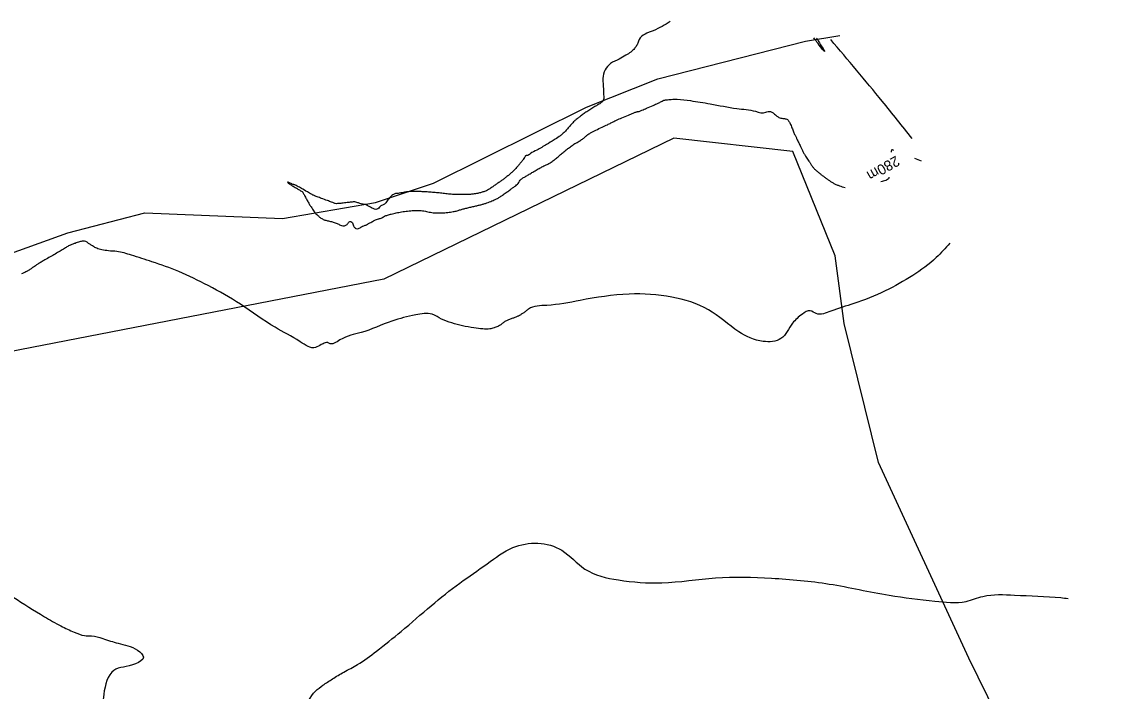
# Model space of a CAD drawing. Extents: x -478495 to -472450, y -1118050 to -1113745.
# Drawn here: x -473729.7 to -473541.9, y -1114845.9 to -1114729.7 of the extents above; entities that cross this region are included whole.
import ezdxf

# ---------------------------------------------------------------- set-up
doc = ezdxf.new("R2010")
doc.units = 0
for name, color, linetype in [('hranice kú', 7, 'Continuous'), ('ObPÚ', 7, 'Continuous'), ('vodní plochy', 7, 'Continuous'), ('Vrstevnice_hlavni', 7, 'Continuous'), ('Vrstevnice_popis', 7, 'Continuous'), ('Vrstevnice_vedlejsi', 7, 'Continuous')]:
    doc.layers.add(name, color=color, linetype=linetype)

msp = doc.modelspace()

# ---------------------------------------------------------------- linework, layer by layer
at = {"layer": 'hranice kú'}
for p, q in [((-473616.54, -1114749.9), (-473666.88, -1114774.39)), ((-473595.9, -1114752.21), (-473616.54, -1114749.9)), ((-473588.58, -1114770.34), (-473595.9, -1114752.21)), ((-473587.03, -1114782.1), (-473588.58, -1114770.34)), ((-473666.88, -1114774.39), (-473748.84, -1114790.3)), ((-473581.05, -1114806.21), (-473587.03, -1114782.1)), ((-473565.42, -1114840.17), (-473581.05, -1114806.21)), ((-473541.89, -1114887.92), (-473565.42, -1114840.17))]:
    msp.add_line(p, q, dxfattribs=at)
at = {"layer": 'ObPÚ'}
for p, q in [((-473616.54, -1114749.9), (-473666.88, -1114774.39)), ((-473595.9, -1114752.21), (-473616.54, -1114749.9)), ((-473588.58, -1114770.34), (-473595.9, -1114752.21)), ((-473587.03, -1114782.1), (-473588.58, -1114770.34)), ((-473666.88, -1114774.39), (-473748.84, -1114790.3)), ((-473581.05, -1114806.21), (-473587.03, -1114782.1)), ((-473565.42, -1114840.17), (-473581.05, -1114806.21)), ((-473541.89, -1114887.92), (-473565.42, -1114840.17))]:
    msp.add_line(p, q, dxfattribs=at)
at = {"layer": 'vodní plochy'}
msp.add_lwpolyline([(-473839.68, -1114806.28), (-473828.96, -1114801), (-473821, -1114798.71), (-473811.3, -1114796.4), (-473807.28, -1114795.16), (-473768.45, -1114783.18), (-473752.84, -1114777.56), (-473721.71, -1114766.35), (-473708.35, -1114762.87), (-473684.42, -1114763.85), (-473668.29, -1114761.06), (-473658.27, -1114757.72), (-473631.7, -1114744.51), (-473619.32, -1114739.64), (-473593.72, -1114733.1), (-473587.75, -1114732.09)], dxfattribs=at)
at = {"layer": 'Vrstevnice_hlavni'}
msp.add_line((-473574.83, -1114753.4), (-473573.68, -1114753.83), dxfattribs=at)
for points in [[(-473617.2, -1114729.7), (-473620.15, -1114731.27), (-473622.56, -1114732.78), (-473622.79, -1114733.42), (-473623.11, -1114733.99), (-473623.53, -1114734.51), (-473624.04, -1114734.98), (-473624.87, -1114735.54), (-473626.04, -1114736.2), (-473627.53, -1114736.95), (-473628.48, -1114738.07), (-473628.89, -1114739.54), (-473628.76, -1114741.38), (-473628.73, -1114742.66), (-473628.81, -1114743.4), (-473628.99, -1114743.6), (-473629.15, -1114743.75), (-473629.29, -1114743.86), (-473629.41, -1114743.94), (-473629.73, -1114744.13), (-473630.26, -1114744.45), (-473630.99, -1114744.88), (-473631.67, -1114745.32), (-473632.3, -1114745.76), (-473632.88, -1114746.21), (-473633.33, -1114746.55), (-473633.64, -1114746.8), (-473633.82, -1114746.94), (-473634.1, -1114747.24), (-473634.5, -1114747.68), (-473635, -1114748.28), (-473635.5, -1114748.81), (-473635.98, -1114749.27), (-473636.46, -1114749.65), (-473637.35, -1114750.23), (-473638.64, -1114751.01), (-473640.34, -1114751.98), (-473641.47, -1114752.62), (-473642.05, -1114752.94), (-473642.06, -1114752.94), (-473642.09, -1114752.94), (-473642.15, -1114752.95), (-473642.23, -1114752.96), (-473642.29, -1114752.99), (-473642.33, -1114753.03), (-473642.34, -1114753.09), (-473642.46, -1114753.28), (-473642.69, -1114753.6), (-473643.04, -1114754.06), (-473643.37, -1114754.48), (-473643.69, -1114754.85), (-473643.99, -1114755.19), (-473644.36, -1114755.56), (-473644.78, -1114755.95), (-473645.27, -1114756.38), (-473645.75, -1114756.77), (-473646.23, -1114757.12), (-473646.7, -1114757.45), (-473647.19, -1114757.79), (-473647.71, -1114758.16), (-473648.24, -1114758.54), (-473648.7, -1114758.83), (-473649.09, -1114759.04), (-473649.39, -1114759.15), (-473649.69, -1114759.26), (-473649.98, -1114759.35), (-473650.26, -1114759.43), (-473650.59, -1114759.51), (-473650.97, -1114759.58)], [(-473591.82, -1114732.54), (-473591.73, -1114732.69), (-473590.44, -1114734.87), (-473591.74, -1114733.26), (-473592.29, -1114732.49)], [(-473575.23, -1114750), (-473580.41, -1114743.51), (-473589.36, -1114732.82)], [(-473622.72, -1114745.29), (-473622.57, -1114745.27), (-473622.09, -1114745.08), (-473621.29, -1114744.74), (-473620.16, -1114744.24), (-473619.3, -1114743.84), (-473618.72, -1114743.56), (-473618.41, -1114743.39), (-473617.85, -1114743.27), (-473617.03, -1114743.19), (-473615.96, -1114743.16), (-473613.7, -1114743.41), (-473610.25, -1114743.95), (-473605.62, -1114744.77), (-473602.4, -1114745.26), (-473600.61, -1114745.43), (-473600.23, -1114745.27), (-473599.81, -1114745.31), (-473599.34, -1114745.55), (-473598.82, -1114746), (-473598.37, -1114746.31), (-473597.99, -1114746.46), (-473597.67, -1114746.48), (-473597.38, -1114746.52), (-473597.11, -1114746.58), (-473596.87, -1114746.68), (-473596.6, -1114747), (-473596.32, -1114747.54), (-473596.01, -1114748.31), (-473595.73, -1114748.98), (-473595.48, -1114749.54), (-473595.26, -1114750), (-473595.06, -1114750.39), (-473594.89, -1114750.72), (-473594.74, -1114750.99), (-473594.57, -1114751.35), (-473594.35, -1114751.8), (-473594.11, -1114752.36), (-473593.86, -1114752.83), (-473593.62, -1114753.23), (-473593.38, -1114753.56), (-473593.13, -1114753.92), (-473592.86, -1114754.32), (-473592.58, -1114754.76), (-473592.24, -1114755.18), (-473591.83, -1114755.57), (-473591.37, -1114755.95), (-473590.93, -1114756.3), (-473590.51, -1114756.62), (-473590.11, -1114756.91), (-473589.7, -1114757.2), (-473589.26, -1114757.48), (-473588.8, -1114757.76), (-473588.32, -1114758), (-473587.84, -1114758.19), (-473586.85, -1114758.47)], [(-473676.78, -1114764.22), (-473676.12, -1114764.36), (-473675.47, -1114764.54), (-473674.84, -1114764.78), (-473674.22, -1114765.07), (-473673.69, -1114765.11), (-473673.25, -1114764.91), (-473672.9, -1114764.46), (-473672.59, -1114764.37), (-473672.31, -1114764.64), (-473672.06, -1114765.26), (-473671.72, -1114765.58), (-473671.28, -1114765.6), (-473670.74, -1114765.31), (-473670.35, -1114765.11), (-473670.1, -1114765.01), (-473670.01, -1114764.99), (-473669.73, -1114764.87), (-473669.28, -1114764.63), (-473668.66, -1114764.29), (-473668.17, -1114764.05), (-473667.82, -1114763.91), (-473667.61, -1114763.87), (-473667.36, -1114763.78), (-473667.07, -1114763.65), (-473666.75, -1114763.47), (-473666.25, -1114763.28), (-473665.57, -1114763.08), (-473664.72, -1114762.88), (-473663.78, -1114762.71), (-473662.76, -1114762.57), (-473661.65, -1114762.47), (-473660.62, -1114762.48), (-473659.67, -1114762.58), (-473658.79, -1114762.78), (-473657.85, -1114762.89), (-473656.84, -1114762.89), (-473655.77, -1114762.79), (-473654.87, -1114762.67), (-473654.14, -1114762.51), (-473653.58, -1114762.33), (-473652.96, -1114762.16), (-473652.3, -1114762), (-473651.58, -1114761.83), (-473650.92, -1114761.68), (-473650.31, -1114761.53), (-473649.76, -1114761.39), (-473649.25, -1114761.23), (-473648.77, -1114761.07), (-473648.33, -1114760.89), (-473647.92, -1114760.71), (-473647.53, -1114760.54), (-473647.16, -1114760.37), (-473646.7, -1114760.1), (-473646.14, -1114759.72), (-473645.48, -1114759.25), (-473644.91, -1114758.83), (-473644.41, -1114758.47), (-473643.99, -1114758.17), (-473643.68, -1114757.89), (-473643.46, -1114757.62), (-473643.35, -1114757.37), (-473643.11, -1114757.1), (-473642.74, -1114756.82), (-473642.24, -1114756.53), (-473641.66, -1114756.19), (-473641.01, -1114755.8), (-473640.27, -1114755.36), (-473639.59, -1114754.99), (-473638.97, -1114754.67), (-473638.41, -1114754.42), (-473637.84, -1114754.08), (-473637.25, -1114753.65), (-473636.64, -1114753.14), (-473636.05, -1114752.65), (-473635.49, -1114752.18), (-473634.96, -1114751.74), (-473634.37, -1114751.3), (-473633.72, -1114750.87), (-473633, -1114750.45), (-473632.41, -1114750.07), (-473631.95, -1114749.71), (-473631.6, -1114749.39), (-473631, -1114748.99), (-473630.12, -1114748.53), (-473628.98, -1114748), (-473628.1, -1114747.58), (-473627.48, -1114747.27), (-473627.11, -1114747.08), (-473626.49, -1114746.78), (-473625.59, -1114746.4), (-473624.42, -1114745.91), (-473623.6, -1114745.57), (-473623.13, -1114745.39), (-473623, -1114745.35), (-473622.86, -1114745.31), (-473622.72, -1114745.29)], [(-473578.38, -1114752.06), (-473578.66, -1114751.96), (-473578.77, -1114751.97), (-473578.83, -1114752.05), (-473578.89, -1114752.34)], [(-473650.97, -1114759.58), (-473651.38, -1114759.63), (-473651.99, -1114759.68), (-473652.79, -1114759.7), (-473653.79, -1114759.71), (-473654.75, -1114759.68), (-473655.68, -1114759.61), (-473656.59, -1114759.5), (-473657.51, -1114759.4), (-473658.43, -1114759.32), (-473659.37, -1114759.26), (-473660.21, -1114759.21), (-473660.95, -1114759.17), (-473661.6, -1114759.15), (-473662.26, -1114759.18), (-473662.95, -1114759.25), (-473663.66, -1114759.38), (-473664.21, -1114759.47), (-473664.6, -1114759.53), (-473664.82, -1114759.54), (-473665.07, -1114759.63), (-473665.33, -1114759.78), (-473665.62, -1114760.01), (-473665.89, -1114760.28), (-473666.16, -1114760.61), (-473666.41, -1114760.98), (-473666.65, -1114761.26), (-473666.89, -1114761.44), (-473667.13, -1114761.52), (-473667.38, -1114761.68), (-473667.63, -1114761.9), (-473667.91, -1114762.19), (-473668.27, -1114762.27), (-473668.74, -1114762.15), (-473669.31, -1114761.82), (-473669.75, -1114761.59), (-473670.08, -1114761.45), (-473670.29, -1114761.42), (-473670.6, -1114761.35), (-473671.01, -1114761.24), (-473671.54, -1114761.08), (-473671.91, -1114760.98), (-473672.13, -1114760.94), (-473672.2, -1114760.96), (-473672.57, -1114761.02), (-473673.23, -1114761.1), (-473674.18, -1114761.22), (-473674.88, -1114761.28), (-473675.3, -1114761.27), (-473675.47, -1114761.2), (-473675.92, -1114761.02), (-473676.66, -1114760.75), (-473677.69, -1114760.37), (-473678.42, -1114760.1), (-473678.84, -1114759.94), (-473678.96, -1114759.89), (-473679.39, -1114759.66), (-473680.12, -1114759.24), (-473681.16, -1114758.64), (-473681.89, -1114758.23), (-473682.31, -1114758.02), (-473682.42, -1114758), (-473682.51, -1114757.98), (-473682.6, -1114757.96), (-473682.66, -1114757.93), (-473682.83, -1114757.85), (-473683.09, -1114757.74), (-473683.46, -1114757.57), (-473683.58, -1114757.55), (-473683.46, -1114757.68), (-473683.1, -1114757.94), (-473682.84, -1114758.13), (-473682.68, -1114758.23), (-473682.62, -1114758.25), (-473682.41, -1114758.37), (-473682.04, -1114758.59), (-473681.52, -1114758.91), (-473681.16, -1114759.14), (-473680.95, -1114759.28), (-473680.92, -1114759.34), (-473680.78, -1114759.58), (-473680.55, -1114760), (-473680.23, -1114760.61), (-473679.9, -1114761.19), (-473679.57, -1114761.73), (-473679.22, -1114762.25), (-473678.99, -1114762.6), (-473678.88, -1114762.77), (-473678.88, -1114762.78), (-473678.86, -1114762.79), (-473678.85, -1114762.83), (-473678.82, -1114762.88), (-473678.65, -1114763.04), (-473678.34, -1114763.32), (-473677.9, -1114763.7), (-473677.38, -1114764.01), (-473676.78, -1114764.22)], [(-473579.28, -1114756.7), (-473579.35, -1114756.97), (-473579.52, -1114757.11), (-473579.82, -1114757.24), (-473580.67, -1114757.48)]]:
    msp.add_spline(points, degree=3, dxfattribs=at)
at = {"layer": 'Vrstevnice_vedlejsi'}
for points in [[(-473568.69, -1114768.16), (-473571.04, -1114770.63), (-473575.13, -1114773.75), (-473579.91, -1114776.42), (-473585.36, -1114778.63), (-473589.35, -1114779.95), (-473591.86, -1114780.36), (-473592.91, -1114779.88), (-473594.27, -1114780.44), (-473595.97, -1114782.04), (-473597.98, -1114784.68), (-473601.09, -1114785.18), (-473605.29, -1114783.51), (-473610.58, -1114779.69), (-473616.93, -1114777.51), (-473624.34, -1114776.98), (-473632.81, -1114778.08), (-473638.61, -1114778.94), (-473641.76, -1114779.57), (-473642.25, -1114779.95), (-473642.7, -1114780.28), (-473643.13, -1114780.55), (-473643.53, -1114780.78), (-473643.99, -1114780.99), (-473644.51, -1114781.18), (-473645.09, -1114781.37), (-473645.62, -1114781.61), (-473646.11, -1114781.92), (-473646.56, -1114782.29), (-473647.11, -1114782.59), (-473647.76, -1114782.84), (-473648.51, -1114783.02), (-473649.68, -1114783.02), (-473651.25, -1114782.84), (-473653.24, -1114782.48), (-473655.1, -1114781.97), (-473656.84, -1114781.3), (-473658.47, -1114780.48), (-473661.34, -1114780.59), (-473665.46, -1114781.65), (-473670.83, -1114783.65), (-473674.48, -1114784.93), (-473676.4, -1114785.51), (-473676.61, -1114785.38), (-473677.06, -1114785.45), (-473677.76, -1114785.74), (-473678.71, -1114786.25), (-473681.36, -1114785.25), (-473685.71, -1114782.74), (-473691.75, -1114778.74), (-473697.33, -1114775.51), (-473702.45, -1114773.06), (-473707.09, -1114771.38), (-473710.67, -1114770.22), (-473713.19, -1114769.58), (-473714.64, -1114769.47), (-473715.81, -1114769.28), (-473716.68, -1114769.03), (-473717.26, -1114768.7), (-473717.76, -1114768.4), (-473718.18, -1114768.12), (-473718.54, -1114767.86), (-473719.03, -1114767.79), (-473719.66, -1114767.89), (-473720.44, -1114768.17), (-473720.98, -1114768.38), (-473721.29, -1114768.5), (-473721.38, -1114768.54), (-473721.7, -1114768.72), (-473722.25, -1114769.05), (-473723.04, -1114769.52), (-473723.87, -1114770.02), (-473724.74, -1114770.52), (-473725.67, -1114771.05), (-473726.29, -1114771.41), (-473726.62, -1114771.6), (-473726.66, -1114771.62), (-473726.89, -1114771.77), (-473727.32, -1114772.07), (-473727.95, -1114772.49), (-473728.41, -1114772.8), (-473728.7, -1114772.99), (-473728.83, -1114773.06), (-473729.16, -1114773.21), (-473729.7, -1114773.44)], [(-473806.43, -1114819.38), (-473806.38, -1114819.37), (-473806.1, -1114819.33), (-473805.58, -1114819.26), (-473804.83, -1114819.16), (-473804.26, -1114819.08), (-473803.86, -1114819.01), (-473803.64, -1114818.96), (-473803.42, -1114818.89), (-473803.18, -1114818.82), (-473802.94, -1114818.73), (-473802.51, -1114818.57), (-473801.87, -1114818.32), (-473801.04, -1114817.99), (-473800.27, -1114817.66), (-473799.56, -1114817.32), (-473798.92, -1114816.98), (-473798.15, -1114816.62), (-473797.28, -1114816.25), (-473796.28, -1114815.85), (-473795.35, -1114815.35), (-473794.47, -1114814.75), (-473793.65, -1114814.03), (-473792.88, -1114813.39), (-473792.17, -1114812.84), (-473791.51, -1114812.36), (-473790.85, -1114811.93), (-473790.2, -1114811.53), (-473789.56, -1114811.17), (-473789.11, -1114810.81), (-473788.85, -1114810.45), (-473788.79, -1114810.08), (-473788.78, -1114809.72), (-473788.8, -1114809.36), (-473788.87, -1114809.01), (-473788.92, -1114808.76), (-473788.96, -1114808.61), (-473788.98, -1114808.58), (-473789.06, -1114808.47), (-473789.2, -1114808.3), (-473789.4, -1114808.07), (-473789.38, -1114807.65), (-473789.15, -1114807.05), (-473788.71, -1114806.27), (-473788.35, -1114805.79), (-473788.06, -1114805.62), (-473787.84, -1114805.76), (-473787.63, -1114805.87), (-473787.42, -1114805.95), (-473787.21, -1114805.99), (-473786.5, -1114806.07), (-473785.28, -1114806.2), (-473783.56, -1114806.36), (-473781.6, -1114806.32), (-473779.4, -1114806.07), (-473776.95, -1114805.61), (-473775.18, -1114805.35), (-473774.08, -1114805.27), (-473773.66, -1114805.39), (-473771.91, -1114806.02), (-473768.82, -1114807.16), (-473764.41, -1114808.8), (-473757.99, -1114812.23), (-473749.54, -1114817.42), (-473739.09, -1114824.39), (-473731.16, -1114829.57), (-473725.76, -1114832.96), (-473722.88, -1114834.56), (-473720.56, -1114835.65), (-473718.79, -1114836.23), (-473717.58, -1114836.3), (-473715.64, -1114836.75), (-473712.97, -1114837.58), (-473709.58, -1114838.79), (-473708.57, -1114839.98), (-473709.95, -1114841.15), (-473713.71, -1114842.29), (-473715.46, -1114846.43), (-473715.18, -1114853.56), (-473712.88, -1114863.69), (-473711.43, -1114870.72), (-473710.84, -1114874.67), (-473711.08, -1114875.52), (-473711.23, -1114876.41), (-473711.26, -1114877.31), (-473711.19, -1114878.25), (-473711.12, -1114879.28), (-473711.05, -1114880.42), (-473710.98, -1114881.65), (-473711.16, -1114883.02), (-473711.59, -1114884.54), (-473712.27, -1114886.19), (-473712.58, -1114888.75), (-473712.5, -1114892.22), (-473712.05, -1114896.6), (-473711.58, -1114899.59), (-473711.1, -1114901.19)], [(-473711.1, -1114901.19), (-473710.6, -1114901.41), (-473710.26, -1114901.53), (-473710.06, -1114901.57), (-473710.01, -1114901.53), (-473709.97, -1114901.49), (-473709.95, -1114901.47), (-473709.94, -1114901.46), (-473709.93, -1114901.44), (-473709.93, -1114901.43), (-473709.93, -1114901.42), (-473709.78, -1114900.89), (-473709.47, -1114899.85), (-473709.01, -1114898.29), (-473708.71, -1114897.24), (-473708.55, -1114896.69), (-473708.55, -1114896.64), (-473708.5, -1114896.23), (-473708.41, -1114895.48), (-473708.27, -1114894.37), (-473708.06, -1114893.47), (-473707.77, -1114892.79), (-473707.4, -1114892.33), (-473706.94, -1114891.55), (-473706.39, -1114890.46), (-473705.74, -1114889.05), (-473705.18, -1114887.94), (-473704.69, -1114887.15), (-473704.29, -1114886.65), (-473703.73, -1114886.18), (-473703.01, -1114885.72), (-473702.14, -1114885.28), (-473701.43, -1114884.84), (-473700.89, -1114884.42), (-473700.52, -1114884.01), (-473700.06, -1114883.38), (-473699.49, -1114882.54), (-473698.82, -1114881.48), (-473698.24, -1114880.31), (-473697.76, -1114879.02), (-473697.36, -1114877.62), (-473697.09, -1114876.65), (-473696.93, -1114876.12), (-473696.88, -1114876.01), (-473696.49, -1114875.69), (-473695.76, -1114875.14), (-473694.69, -1114874.37), (-473693.74, -1114873.74), (-473692.92, -1114873.26), (-473692.23, -1114872.91), (-473690.49, -1114869.83), (-473687.7, -1114864.01), (-473683.85, -1114855.45), (-473680.85, -1114849.41), (-473678.72, -1114845.88), (-473677.43, -1114844.86), (-473675.79, -1114843.76), (-473673.8, -1114842.57), (-473671.44, -1114841.28), (-473668.14, -1114838.94), (-473663.87, -1114835.52), (-473658.65, -1114831.05), (-473653.67, -1114827.13), (-473648.95, -1114823.78), (-473644.48, -1114820.98), (-473640.15, -1114820.2), (-473635.99, -1114821.44), (-473631.98, -1114824.7), (-473626.19, -1114826.58), (-473618.64, -1114827.09), (-473609.32, -1114826.22), (-473599.64, -1114826.28), (-473589.6, -1114827.29), (-473579.21, -1114829.24), (-473571.3, -1114830.25), (-473565.87, -1114830.31), (-473562.94, -1114829.43), (-473557.46, -1114829.21), (-473549.43, -1114829.66), (-473548.19, -1114829.78)]]:
    msp.add_spline(points, degree=3, dxfattribs=at)

# ---------------------------------------------------------------- texts
at = {"layer": 'Vrstevnice_popis'}
msp.add_text(' 280m ', height=1.8, rotation=209.3995, dxfattribs=at).set_placement((-473577.46, -1114752.58))

doc.saveas('drawing.dxf')
